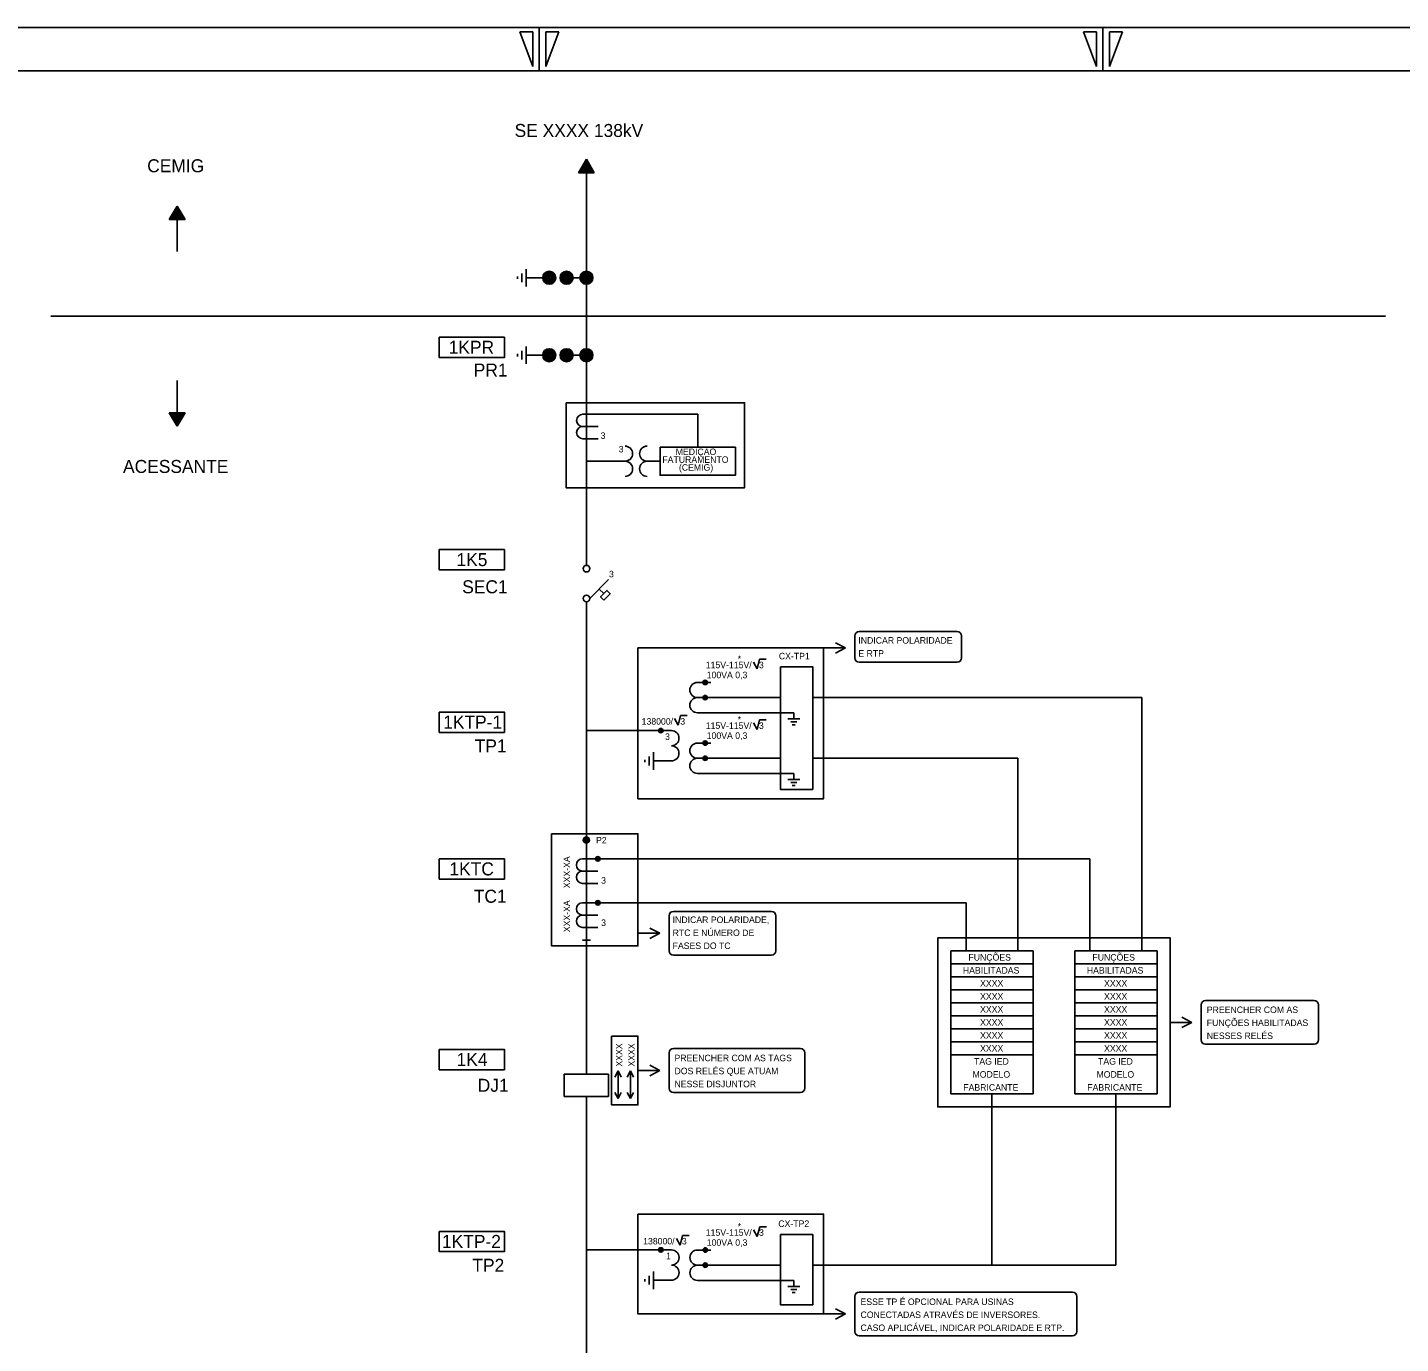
# Model space of a CAD drawing. Extents: x 563 to 1404, y 358 to 952.
# Drawn here: x 785.5 to 1102.2, y 648.4 to 952 of the extents above; entities that cross this region are included whole.
import ezdxf

# ---------------------------------------------------------------- set-up
doc = ezdxf.new("R2010")
doc.units = 0
doc.layers.add('New Level (0)', color=7, linetype='Continuous')

# ---------------------------------------------------------------- blocks, each defined once
blk = doc.blocks.new('_U3')
for p, q in [((-1.47, 0.42), (-0.62, -1.12)), ((-0.62, -1.12), (-0.07, 1.12)), ((-0.07, 1.12), (1.47, 1.12))]:
    blk.add_line(p, q)

msp = doc.modelspace()

# ---------------------------------------------------------------- linework, layer by layer
for p, q in [((914.46, 921.55), (912.65, 918.45)), ((914.46, 921.34), (912.83, 918.55)), ((912.83, 918.55), (916.08, 918.55)), ((914.46, 921.14), (913.01, 918.66)), ((913.01, 918.66), (915.9, 918.66)), ((914.46, 920.93), (913.19, 918.76)), ((913.19, 918.76), (915.72, 918.76)), ((914.46, 920.72), (913.37, 918.86)), ((913.37, 918.86), (915.54, 918.86)), ((914.46, 920.52), (913.55, 918.97)), ((913.55, 918.97), (915.36, 918.97)), ((914.46, 920.31), (913.73, 919.07)), ((913.73, 919.07), (915.18, 919.07)), ((914.46, 920.1), (913.91, 919.17)), ((913.91, 919.17), (915, 919.17)), ((914.46, 919.9), (914.09, 919.28)), ((914.09, 919.28), (914.82, 919.28)), ((914.46, 919.69), (914.27, 919.38)), ((914.27, 919.38), (914.64, 919.38)), ((916.27, 918.45), (914.46, 921.55)), ((916.08, 918.55), (914.46, 921.34)), ((915.9, 918.66), (914.46, 921.14)), ((915.72, 918.76), (914.46, 920.93)), ((915.54, 918.86), (914.46, 920.72)), ((915.36, 918.97), (914.46, 920.52)), ((915.18, 919.07), (914.46, 920.31)), ((915, 919.17), (914.46, 920.1)), ((914.82, 919.28), (914.46, 919.9)), ((914.64, 919.38), (914.46, 919.69)), ((912.65, 918.45), (916.27, 918.45)), ((912.65, 918.45), (916.27, 918.45)), ((914.46, 827.91), (914.46, 918.45)), ((820.05, 910.76), (818.24, 907.66)), ((820.05, 910.56), (818.42, 907.77)), ((820.05, 910.35), (818.6, 907.87)), ((820.05, 910.14), (818.78, 907.97)), ((820.05, 909.94), (818.96, 908.08)), ((820.05, 909.73), (819.14, 908.18)), ((820.05, 909.52), (819.32, 908.28)), ((820.05, 909.32), (819.5, 908.39)), ((820.05, 909.11), (819.68, 908.49)), ((821.86, 907.66), (820.05, 910.76)), ((821.67, 907.77), (820.05, 910.56)), ((821.49, 907.87), (820.05, 910.35)), ((821.31, 907.97), (820.05, 910.14)), ((821.13, 908.08), (820.05, 909.94)), ((820.95, 908.18), (820.05, 909.73)), ((820.77, 908.28), (820.05, 909.52)), ((820.59, 908.39), (820.05, 909.32)), ((820.41, 908.49), (820.05, 909.11)), ((818.24, 907.66), (821.86, 907.66)), ((818.24, 907.66), (821.86, 907.66)), ((818.42, 907.77), (821.67, 907.77)), ((818.6, 907.87), (821.49, 907.87)), ((818.78, 907.97), (821.31, 907.97)), ((818.96, 908.08), (821.13, 908.08)), ((819.14, 908.18), (820.95, 908.18)), ((819.32, 908.28), (820.77, 908.28)), ((819.5, 908.39), (820.59, 908.39)), ((819.68, 908.49), (820.41, 908.49)), ((820.05, 908.9), (819.86, 908.59)), ((819.86, 908.59), (820.23, 908.59)), ((820.23, 908.59), (820.05, 908.9)), ((820.05, 900.25), (820.05, 907.66)), ((898.55, 894.55), (898.55, 893.95)), ((898.55, 894.25), (898.55, 894.25)), ((899.55, 895.25), (899.55, 893.25)), ((900.55, 892.25), (900.55, 896.25)), ((901.87, 894.25), (900.55, 894.25)), ((905.87, 894.25), (901.87, 894.25)), ((914.46, 894.25), (909.87, 894.25)), ((1098.74, 885.38), (790.91, 885.38)), ((899.55, 877.36), (899.55, 875.36)), ((900.55, 874.36), (900.55, 878.36)), ((898.55, 876.66), (898.55, 876.06)), ((898.55, 876.36), (898.55, 876.36)), ((901.87, 876.36), (900.55, 876.36)), ((905.87, 876.36), (901.87, 876.36)), ((914.46, 876.36), (909.87, 876.36)), ((820.05, 870.52), (820.05, 863.1)), ((821.86, 863.1), (818.24, 863.1)), ((818.24, 863.1), (820.05, 860)), ((821.86, 863.1), (818.24, 863.1)), ((821.67, 863), (818.42, 863)), ((818.42, 863), (820.05, 860.21)), ((821.49, 862.9), (818.6, 862.9)), ((818.6, 862.9), (820.05, 860.42)), ((821.31, 862.79), (818.78, 862.79)), ((818.78, 862.79), (820.05, 860.62)), ((821.13, 862.69), (818.96, 862.69)), ((818.96, 862.69), (820.05, 860.83)), ((820.95, 862.59), (819.14, 862.59)), ((819.14, 862.59), (820.05, 861.04)), ((820.77, 862.48), (819.32, 862.48)), ((819.32, 862.48), (820.05, 861.24)), ((820.59, 862.38), (819.5, 862.38)), ((819.5, 862.38), (820.05, 861.45)), ((820.41, 862.28), (819.68, 862.28)), ((819.68, 862.28), (820.05, 861.66)), ((820.23, 862.17), (819.86, 862.17)), ((819.86, 862.17), (820.05, 861.86)), ((820.05, 860), (821.86, 863.1)), ((820.05, 860.21), (821.67, 863)), ((820.05, 860.42), (821.49, 862.9)), ((820.05, 860.62), (821.31, 862.79)), ((820.05, 860.83), (821.13, 862.69)), ((820.05, 861.04), (820.95, 862.59)), ((820.05, 861.24), (820.77, 862.48)), ((820.05, 861.45), (820.59, 862.38)), ((820.05, 861.66), (820.41, 862.28)), ((820.05, 861.86), (820.23, 862.17)), ((913.61, 862.76), (917.15, 862.76)), ((917.15, 862.76), (940.14, 862.76)), ((913.61, 859.93), (917.15, 859.93)), ((913.61, 857.09), (917.15, 857.09)), ((914.52, 851.91), (923.36, 851.91)), ((928.46, 851.91), (931.46, 851.91)), ((919.56, 824.61), (915.22, 820.27)), ((918.45, 821.38), (917.39, 822.44)), ((914.46, 819.5), (914.46, 710.55)), ((940.05, 800.9), (943.16, 800.9)), ((940.05, 797.4), (959.19, 797.4)), ((966.67, 797.4), (1042.59, 797.4)), ((1042.59, 797.4), (1042.59, 739)), ((940.05, 793.9), (962.28, 793.9)), ((963.68, 792.5), (960.88, 792.5)), ((962.28, 793.9), (962.28, 792.5)), ((914.46, 789.8), (934.05, 789.8)), ((961.58, 791.8), (962.98, 791.8)), ((961.94, 791.1), (962.62, 791.1)), ((940.05, 786.91), (943.16, 786.91)), ((927.92, 783.04), (927.92, 782.5)), ((928.93, 781.78), (928.93, 783.82)), ((929.96, 784.85), (929.96, 780.75)), ((934.05, 782.8), (929.96, 782.8)), ((940.05, 783.41), (943.16, 783.41)), ((940.05, 783.41), (959.19, 783.41)), ((966.67, 783.41), (1013.99, 783.41)), ((1013.99, 783.41), (1013.99, 739)), ((940.05, 779.91), (962.28, 779.91)), ((962.28, 779.91), (962.28, 778.51)), ((963.68, 778.51), (960.88, 778.51)), ((961.58, 777.81), (962.98, 777.81)), ((961.94, 777.11), (962.62, 777.11)), ((913.55, 760.21), (1030.61, 760.21)), ((1030.61, 760.21), (1030.61, 739)), ((913.55, 757.38), (917.09, 757.38)), ((913.55, 754.55), (917.09, 754.55)), ((913.55, 750.07), (1002.01, 750.07)), ((1002.01, 750.07), (1002.01, 739)), ((913.55, 747.24), (917.09, 747.24)), ((913.55, 744.41), (917.09, 744.41)), ((1017.49, 739), (998.51, 739)), ((998.51, 739), (998.51, 706)), ((1017.49, 739), (1017.49, 706)), ((1046.09, 739), (1027.11, 739)), ((1027.11, 739), (1027.11, 706)), ((1046.09, 739), (1046.09, 706)), ((1017.49, 736), (998.51, 736)), ((1046.09, 736), (1027.11, 736)), ((1017.49, 733), (998.51, 733)), ((1046.09, 733), (1027.11, 733)), ((1017.49, 730), (998.51, 730)), ((1046.09, 730), (1027.11, 730)), ((1017.49, 727), (998.51, 727)), ((1046.09, 727), (1027.11, 727)), ((1017.49, 724), (998.51, 724)), ((1046.09, 724), (1027.11, 724)), ((1017.49, 721), (998.51, 721)), ((1017.49, 721), (998.51, 721)), ((1046.09, 721), (1027.11, 721)), ((1046.09, 721), (1027.11, 721)), ((1017.49, 718), (998.51, 718)), ((1046.09, 718), (1027.11, 718)), ((1017.49, 715), (998.51, 715)), ((1046.09, 715), (1027.11, 715)), ((909.34, 705.43), (909.34, 710.55)), ((909.34, 710.55), (919.58, 710.55)), ((919.58, 710.55), (919.58, 705.43)), ((921.74, 711.3), (921.03, 709.89)), ((921.74, 704.93), (921.74, 711.3)), ((921.74, 711.3), (922.44, 709.89)), ((924.59, 711.3), (923.88, 709.89)), ((924.59, 704.93), (924.59, 711.3)), ((924.59, 711.3), (925.29, 709.89)), ((921.74, 704.93), (921.03, 706.35)), ((921.74, 704.93), (922.44, 706.35)), ((924.59, 704.93), (923.88, 706.35)), ((924.59, 704.93), (925.29, 706.35)), ((919.58, 705.43), (909.34, 705.43)), ((914.46, 705.43), (914.46, 614.76)), ((1017.49, 706), (998.51, 706)), ((1008, 706), (1008, 666.5)), ((1046.09, 706), (1027.11, 706)), ((1036.6, 706), (1036.6, 666.5)), ((914.46, 670.03), (934.06, 670.03)), ((940.06, 670), (943.17, 670)), ((940.06, 666.5), (959.19, 666.5)), ((966.67, 666.5), (1036.6, 666.5)), ((927.93, 663.27), (927.93, 662.73)), ((928.94, 662.01), (928.94, 664.05)), ((929.96, 665.08), (929.96, 660.98)), ((934.06, 663.03), (929.96, 663.03)), ((940.06, 663), (962.29, 663)), ((962.29, 663), (962.29, 661.6)), ((963.69, 661.6), (960.89, 661.6)), ((961.59, 660.9), (962.99, 660.9)), ((961.94, 660.2), (962.63, 660.2))]:
    msp.add_line(p, q)
msp.add_lwpolyline([(918.48, 819.88), (917.72, 820.64), (919.19, 822.12), (919.96, 821.35)], close=True)
for centre, radius in [((905.87, 894.25), 1.5), ((905.87, 894.25), 1.25), ((905.87, 894.25), 1), ((905.87, 894.25), 0.75), ((905.87, 894.25), 0.5), ((905.87, 894.25), 0.25), ((909.87, 894.25), 1.5), ((909.87, 894.25), 1.25), ((909.87, 894.25), 1), ((909.87, 894.25), 0.75), ((909.87, 894.25), 0.5), ((909.87, 894.25), 0.25), ((914.46, 894.25), 1.5), ((914.46, 894.25), 1.25), ((914.46, 894.25), 1), ((914.46, 894.25), 0.75), ((914.46, 894.25), 0.5), ((914.46, 894.25), 0.25), ((905.87, 876.36), 1.5), ((905.87, 876.36), 1.25), ((905.87, 876.36), 1), ((909.87, 876.36), 1.5), ((909.87, 876.36), 1.25), ((909.87, 876.36), 1), ((914.46, 876.36), 1.5), ((914.46, 876.36), 1.25), ((914.46, 876.36), 1), ((905.87, 876.36), 0.75), ((905.87, 876.36), 0.5), ((905.87, 876.36), 0.25), ((909.87, 876.36), 0.75), ((909.87, 876.36), 0.5), ((909.87, 876.36), 0.25), ((914.46, 876.36), 0.75), ((914.46, 876.36), 0.5), ((914.46, 876.36), 0.25), ((914.46, 827.14), 0.768), ((914.46, 820.27), 0.768), ((941.85, 800.9), 0.511), ((941.85, 800.9), 0.288), ((941.85, 797.4), 0.511), ((941.85, 797.4), 0.288), ((931.61, 789.8), 0.511), ((931.61, 789.8), 0.288), ((941.85, 786.91), 0.511), ((941.85, 786.91), 0.288), ((941.85, 783.41), 0.511), ((941.85, 783.41), 0.288), ((914.45, 764.55), 0.729), ((914.46, 764.54), 0.511), ((914.46, 764.54), 0.288), ((917.09, 760.21), 0.511), ((917.09, 760.21), 0.288), ((917.09, 750.07), 0.511), ((917.09, 750.07), 0.288), ((931.62, 670.03), 0.511), ((931.62, 670.03), 0.288), ((941.86, 670), 0.511), ((941.86, 670), 0.288), ((941.86, 666.5), 0.511), ((941.86, 666.5), 0.288)]:
    msp.add_circle(centre, radius)
for centre, radius, start, end in [((913.61, 861.34), 1.42, 90, 270), ((913.61, 858.51), 1.42, 90, 270), ((923.36, 853.66), 1.75, 270, 90), ((928.46, 853.66), 1.75, 90, 270), ((923.36, 850.16), 1.75, 270, 90), ((928.46, 850.16), 1.75, 90, 270), ((940.05, 799.15), 1.75, 90, 270), ((940.05, 795.65), 1.75, 90, 270), ((934.05, 788.05), 1.75, 270, 90), ((934.05, 784.55), 1.75, 270, 90), ((940.05, 785.16), 1.75, 90, 270), ((940.05, 781.66), 1.75, 90, 270), ((913.55, 758.8), 1.42, 90, 270), ((913.55, 755.97), 1.42, 90, 270), ((913.55, 748.66), 1.42, 90, 270), ((913.55, 745.83), 1.42, 90, 270), ((934.06, 668.28), 1.75, 270, 90), ((940.06, 668.25), 1.75, 90, 270), ((934.06, 664.78), 1.75, 270, 90), ((940.06, 664.75), 1.75, 90, 270)]:
    msp.add_arc(centre, radius, start, end)
at = {"layer": 'New Level (0)'}
for p, q in [((1403.58, 951.96), (562.58, 951.96)), ((1403.58, 951.96), (562.58, 951.96)), ((902.08, 950.96), (899.08, 950.96)), ((899.08, 950.96), (902.08, 942.96)), ((902.08, 942.96), (902.08, 950.96)), ((903.58, 951.96), (903.58, 941.96)), ((905.08, 942.96), (905.08, 950.96)), ((905.08, 950.96), (908.08, 950.96)), ((908.08, 950.96), (905.08, 942.96)), ((1032.08, 950.96), (1029.08, 950.96)), ((1029.08, 950.96), (1032.08, 942.96)), ((1032.08, 942.96), (1032.08, 950.96)), ((1033.58, 951.96), (1033.58, 941.96)), ((1035.08, 942.96), (1035.08, 950.96)), ((1035.08, 950.96), (1038.08, 950.96)), ((1038.08, 950.96), (1035.08, 942.96)), ((1393.58, 941.96), (572.58, 941.96)), ((940.14, 855.14), (940.14, 862.76)), ((976.35, 806.55), (976.35, 811.62)), ((977.35, 812.62), (984.7, 812.62)), ((984.7, 812.62), (999.96, 812.62)), ((1000.96, 811.62), (1000.96, 806.55)), ((969.16, 808.86), (974.19, 808.86)), ((974.19, 808.86), (971.89, 810.07)), ((974.19, 808.86), (971.89, 807.65)), ((999.96, 805.55), (977.35, 805.55)), ((934.51, 748.1), (941.86, 748.1)), ((941.86, 748.1), (957.12, 748.1)), ((933.51, 738.99), (933.51, 747.1)), ((958.12, 747.1), (958.12, 738.99)), ((913.56, 741.46), (915.36, 741.46)), ((926.32, 743.04), (931.35, 743.04)), ((931.35, 743.04), (929.05, 744.25)), ((931.35, 743.04), (929.05, 741.83)), ((957.12, 737.99), (934.51, 737.99)), ((1056.28, 718.45), (1056.28, 726.56)), ((1057.28, 727.56), (1064.63, 727.56)), ((1064.63, 727.56), (1082.29, 727.56)), ((1083.29, 726.56), (1083.29, 718.45)), ((1049.09, 722.5), (1054.12, 722.5)), ((1054.12, 722.5), (1051.83, 723.71)), ((1054.12, 722.5), (1051.83, 721.3)), ((934.51, 716.45), (941.86, 716.45)), ((941.86, 716.45), (963.8, 716.45)), ((1082.29, 717.45), (1057.28, 717.45)), ((933.51, 707.33), (933.51, 715.45)), ((964.8, 715.45), (964.8, 707.33)), ((926.32, 711.39), (931.35, 711.39)), ((931.35, 711.39), (929.05, 712.6)), ((931.35, 711.39), (929.05, 710.18)), ((963.8, 706.33), (934.51, 706.33)), ((976.35, 651.19), (976.35, 659.31)), ((977.35, 660.31), (984.71, 660.31)), ((984.71, 660.31), (1026.54, 660.31)), ((1027.54, 659.31), (1027.54, 651.19)), ((974.2, 655.25), (971.9, 656.46)), ((969.17, 655.25), (974.2, 655.25)), ((974.2, 655.25), (971.9, 654.04)), ((1026.54, 650.19), (977.35, 650.19))]:
    msp.add_line(p, q, dxfattribs=at)
for points in [[(880.5, 880.52), (895.52, 880.52), (895.52, 875.84), (880.5, 875.84)], [(909.78, 865.42), (950.94, 865.42), (950.94, 845.81), (909.78, 845.81)], [(931.46, 855.14), (948.81, 855.14), (948.81, 848.67), (931.46, 848.67)], [(880.5, 831.54), (895.52, 831.54), (895.52, 826.86), (880.5, 826.86)], [(926.32, 808.86), (969.16, 808.86), (969.16, 774.07), (926.32, 774.07)], [(959.19, 804.5), (966.67, 804.5), (966.67, 776.21), (959.19, 776.21)], [(880.5, 794.07), (895.52, 794.07), (895.52, 789.39), (880.5, 789.39)], [(906.42, 766.02), (926.32, 766.02), (926.32, 740.12), (906.42, 740.12)], [(880.5, 760.21), (895.52, 760.21), (895.52, 755.53), (880.5, 755.53)], [(995.51, 742), (1049.09, 742), (1049.09, 703), (995.51, 703)], [(920.25, 719.33), (926.32, 719.33), (926.32, 703.45), (920.25, 703.45)], [(880.5, 716.26), (895.52, 716.26), (895.52, 711.58), (880.5, 711.58)], [(926.33, 678.3), (969.17, 678.3), (969.17, 655.25), (926.33, 655.25)], [(880.5, 674.3), (895.52, 674.3), (895.52, 669.62), (880.5, 669.62)], [(959.19, 673.6), (966.67, 673.6), (966.67, 657.39), (959.19, 657.39)]]:
    msp.add_lwpolyline(points, close=True, dxfattribs=at)
for centre, start, end in [((977.35, 811.62), 90, 180), ((999.96, 811.62), 0, 90), ((977.35, 806.55), 180, 270), ((999.96, 806.55), 270, 0), ((934.51, 747.1), 90, 180), ((957.12, 747.1), 0, 90), ((934.51, 738.99), 180, 270), ((957.12, 738.99), 270, 0), ((1057.28, 726.56), 90, 180), ((1082.29, 726.56), 0, 90), ((934.51, 715.45), 90, 180), ((963.8, 715.45), 0, 90), ((1057.28, 718.45), 180, 270), ((1082.29, 718.45), 270, 0), ((934.51, 707.33), 180, 270), ((963.8, 707.33), 270, 0), ((977.35, 659.31), 90, 180), ((1026.54, 659.31), 0, 90), ((977.35, 651.19), 180, 270), ((1026.54, 651.19), 270, 0)]:
    msp.add_arc(centre, 1, start, end, dxfattribs=at)

# ---------------------------------------------------------------- block references
for p in [(954.48, 805.15), (936.25, 792.13), (954.48, 791.16), (954.49, 674.25), (936.7, 672.26)]:
    msp.add_blockref('_U3', p)

# ---------------------------------------------------------------- texts
for s, height, p in [('SE XXXX 138kV', 3, (897.89, 926.7)), ('CEMIG', 3, (813.14, 918.56)), ('1KPR', 3, (882.68, 876.7)), ('PR1', 3, (888.46, 871.45)), ('3', 1.5, (917.73, 857.06)), ('3', 1.5, (921.9, 853.95)), ('MEDIÇÃO', 1.5, (935.05, 853.34)), ('ACESSANTE', 3, (807.56, 849.21)), ('FATURAMENTO', 1.5, (931.97, 851.54)), ('(CEMIG)', 1.5, (935.79, 849.74)), ('1K5', 3, (884.48, 827.72)), ('3', 1.5, (919.65, 825.14)), ('SEC1', 3, (885.8, 821.46)), ('INDICAR POLARIDADE ', 1.5, (977.18, 809.85)), ('CX-TP1', 1.5, (958.84, 806.23)), ('E RTP ', 1.5, (977.18, 806.85)), ('115V-115V/   3', 1.5, (941.98, 804.18)), ('*', 1.5, (949.34, 805.6)), ('100VA 0,3', 1.5, (942.2, 801.87)), ('1KTP-1', 3, (881.41, 790.25)), ('138000/   3', 1.5, (927.19, 791.17)), ('*', 1.5, (949.34, 791.62)), ('3', 1.5, (932.59, 787.65)), ('115V-115V/   3', 1.5, (941.98, 790.19)), ('100VA 0,3', 1.5, (942.2, 787.88)), ('TP1', 3, (888.69, 784.75)), ('P2', 1.5, (916.67, 763.77)), ('1KTC', 3, (882.85, 756.4)), ('3', 1.5, (917.84, 754.49)), ('TC1', 3, (888.47, 750.08)), ('3', 1.5, (917.84, 744.74)), ('INDICAR POLARIDADE, ', 1.5, (934.34, 745.42)), ('RTC E NÚMERO DE ', 1.5, (934.34, 742.42)), ('FASES DO TC', 1.5, (934.34, 739.42)), ('FUNÇÕES ', 1.5, (1002.57, 736.75)), ('FUNÇÕES ', 1.5, (1031.17, 736.75)), ('HABILITADAS', 1.5, (1001.28, 733.75)), ('HABILITADAS', 1.5, (1029.88, 733.75)), ('XXXX', 1.5, (1005.26, 730.75)), ('XXXX', 1.5, (1033.86, 730.75)), ('XXXX', 1.5, (1005.26, 727.75)), ('XXXX', 1.5, (1033.86, 727.75)), ('XXXX', 1.5, (1005.26, 724.75)), ('XXXX', 1.5, (1033.86, 724.75)), ('PREENCHER COM AS ', 1.5, (1057.55, 724.66)), ('XXXX', 1.5, (1005.26, 721.75)), ('XXXX', 1.5, (1033.86, 721.75)), ('FUNÇÕES HABILITADAS ', 1.5, (1057.55, 721.66)), ('XXXX', 1.5, (1005.26, 718.75)), ('XXXX', 1.5, (1033.86, 718.75)), ('NESSES RELÉS', 1.5, (1057.55, 718.66)), ('XXXX', 1.5, (1005.26, 715.75)), ('XXXX', 1.5, (1033.86, 715.75)), ('1K4', 3, (884.5, 712.44)), ('PREENCHER COM AS TAGS ', 1.5, (934.77, 713.54)), ('TAG IED', 1.5, (1003.87, 712.75)), ('TAG IED', 1.5, (1032.47, 712.75)), ('DJ1', 3, (889.38, 706.49)), ('DOS RELÉS QUE ATUAM ', 1.5, (934.77, 710.54)), ('MODELO', 1.5, (1003.51, 709.75)), ('MODELO', 1.5, (1032.11, 709.75)), ('NESSE DISJUNTOR', 1.5, (934.77, 707.54)), ('FABRICANTE', 1.5, (1001.38, 706.75)), ('FABRICANTE', 1.5, (1029.98, 706.75)), ('115V-115V/   3', 1.5, (941.99, 673.28)), ('*', 1.5, (949.35, 674.7)), ('CX-TP2', 1.5, (958.71, 675.33)), ('1KTP-2', 3, (881.13, 670.48)), ('138000/   3', 1.5, (927.54, 671.29)), ('100VA 0,3', 1.5, (942.21, 670.97)), ('1', 1.5, (932.81, 667.87)), ('TP2', 3, (888.14, 664.98)), ('ESSE TP É OPCIONAL PARA USINAS ', 1.5, (977.68, 657.32)), ('CONECTADAS ATRAVÉS DE INVERSORES.', 1.5, (977.68, 654.32)), ('CASO APLICÁVEL, INDICAR POLARIDADE E RTP.', 1.5, (977.68, 651.32))]:
    msp.add_text(s, height=height).set_placement(p)
for s, p in [('XXX-XA', (910.68, 753.44)), ('XXX-XA', (910.68, 743.3)), ('XXXX', (922.74, 712.3)), ('XXXX', (925.59, 712.3))]:
    msp.add_text(s, height=1.5, rotation=90).set_placement(p)

doc.saveas('drawing.dxf')
